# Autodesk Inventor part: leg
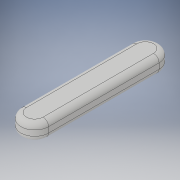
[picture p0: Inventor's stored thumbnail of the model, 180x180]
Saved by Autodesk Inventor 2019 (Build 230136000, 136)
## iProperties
Created: 2020-09
Part Number: leg
Material: 一般
Document SubType Name: Modeling
Designer: kikut
Density: 1 g/cm^3
Appearance: 既定
Author: kikut
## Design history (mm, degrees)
sketch "スケッチ1"
  geometry: L1 (-0.005, -0.04)-(0.005, -0.04); L2 (0.005, -0.04)-(0.005, 0); L3 (0.005, 0)-(-0.005, 0); L4 (-0.005, 0)-(-0.005, -0.04); L5 (-0.005, -0.04)-(0.005, 0); L6 (0.005, -0.04)-(-0.005, 0); L7 (0, -0.055)-(0, 0.015) reference; A1 r 0.005 centre (0, 0) between (0.005, 0) and (-0.005, 0); A2 r 0.005 centre (0, -0.04) between (-0.005, -0.04) and (0.005, -0.04); 2 further points
  constraints: 12 end point, 4 midpoint, 4 point on circle, 2 centre point, 2 parallel, 1 coincident, 1 horizontal, 1 perpendicular, 1 point on line, 1 other
  dimensions: "d0" = 0.01 distance of L2.end L3.end; "d1" = 0.04 distance of L1.end L2.end
extrude "押し出し1" new body sketch "スケッチ1" stored distance "d2" = 0.006; taper "d3" = 0 deg
fillet "フィレット1" dims "d4" = 0.002
node "ソリッド1"
